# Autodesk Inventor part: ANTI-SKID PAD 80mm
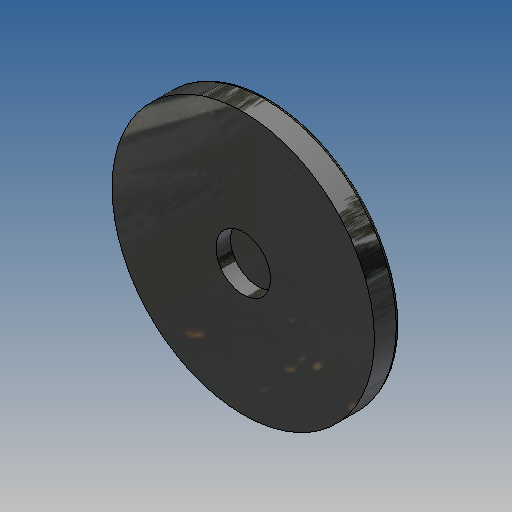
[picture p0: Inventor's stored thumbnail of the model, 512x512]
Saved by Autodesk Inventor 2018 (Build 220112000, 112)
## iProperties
Created: 2007-03
Part Number: ANTI-SKID PAD 80mm
Material: Rubber
Document SubType Name: Modeling
Designer: Andy Moles
Density: 0.93 g/cm^3
Mass: 25.8032 g
Surface Area: 98.1734 cm^2
Volume: 27.7454 cm^3
Appearance: Rubber - Black - Version 1.1
Author: Andy Moles
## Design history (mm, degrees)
sketch "Sketch1"
  geometry: C1 r 36 at (0, 0); 1 further point
  constraints: 1 centre point, 1 coincident
  dimensions: "d0" = 72 diameter of C1
extrude "Extrusion1" new body sketch "Sketch1" distance "d1" = 7; taper "d2" = 0 deg
sketch "Sketch2"
  geometry: C1 r 36 at (0, 0) reference; C2 r 7.5 at (0, 0)
  constraints: 1 centre point, 1 coincident
  dimensions: "d3" = 15 diameter of C2
extrude "Extrusion2" cut sketch "Sketch2" distance "d4" = 4; taper "d5" = 0 deg
fillet "Fillet1" dims "d6" = 1
body "Solid1"
